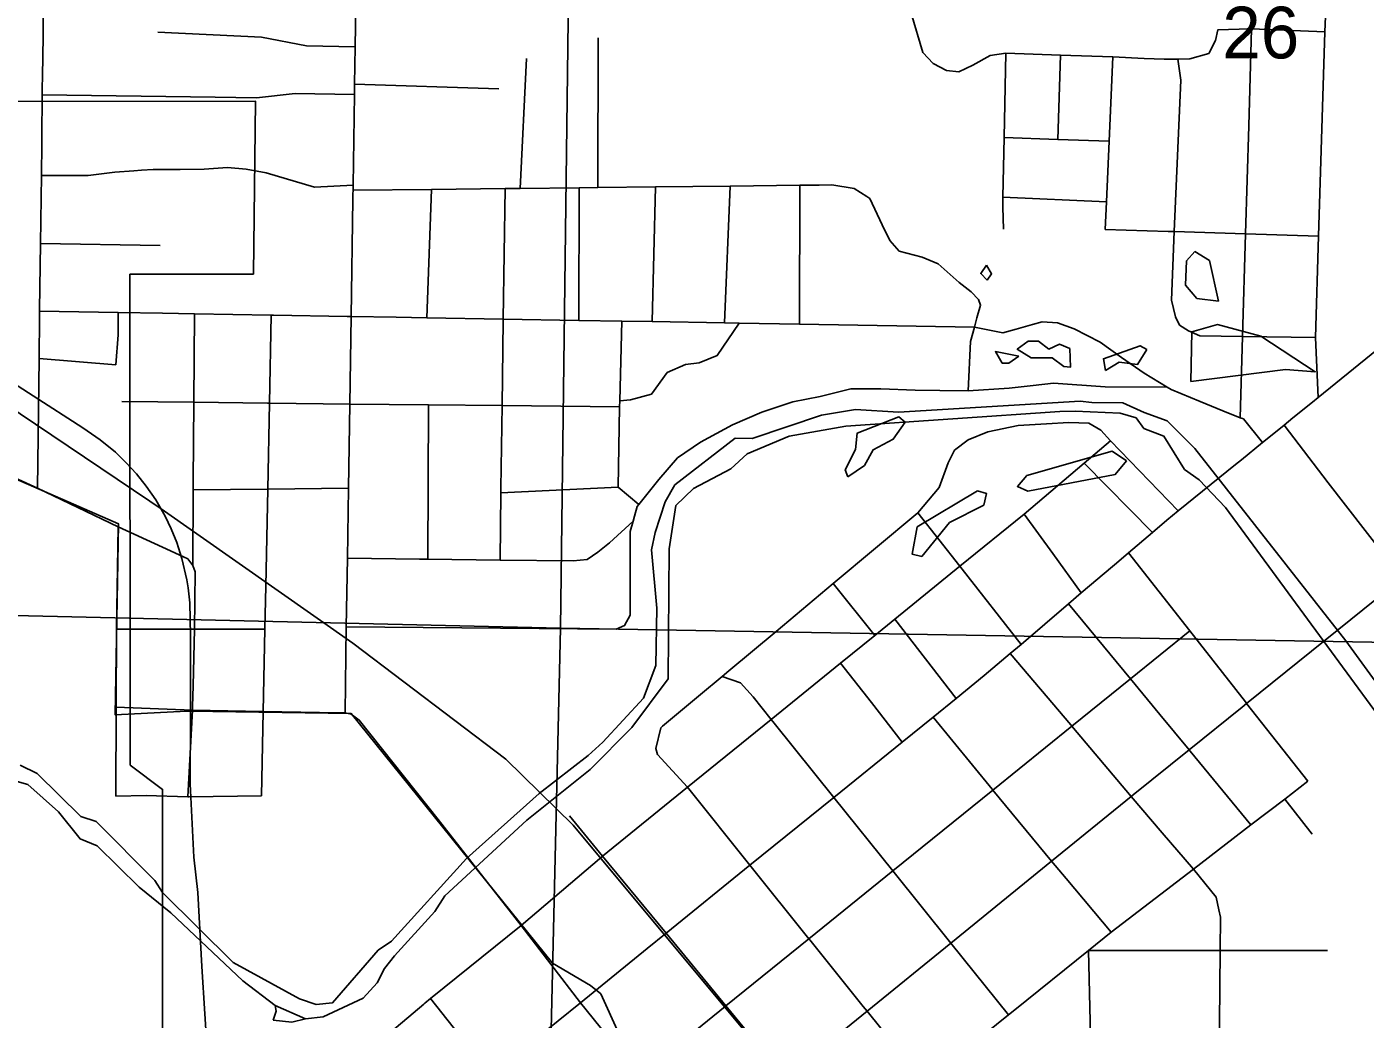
# Model space of a CAD drawing. Extents: x 0 to 68.9, y -26.1 to 22.
# Drawn here: x 4.831 to 5.914, y 17.583 to 18.387 of the extents above; entities that cross this region are included whole.
import ezdxf

# ---------------------------------------------------------------- set-up
doc = ezdxf.new("R2010")
doc.units = 0
for name, color, linetype in [('GM_X_City_Street', 7, 'Continuous'), ('GM_X_Corporation', 7, 'Continuous'), ('GM_X_County_Road', 7, 'Continuous'), ('GM_X_Major_River', 7, 'Continuous'), ('GM_X_Minor_Lake', 7, 'Continuous'), ('GM_X_Rail_Line', 7, 'Continuous'), ('GM_X_Section_Text', 7, 'Continuous'), ('GM_X_State_Route', 7, 'Continuous')]:
    doc.layers.add(name, color=color, linetype=linetype)

msp = doc.modelspace()

# ---------------------------------------------------------------- linework, layer by layer
at = {"layer": 'GM_X_City_Street'}
for p, q in [((5.293, 18.2569), (5.2933, 18.3781)), ((5.6653, 18.2958), (5.6675, 18.364)), ((5.23, 18.2562), (5.2351, 18.3613)), ((5.0961, 18.3405), (5.2127, 18.3369)), ((5.1546, 18.1514), (5.1582, 18.2554)), ((5.2775, 18.1493), (5.2778, 18.2567)), ((5.337, 18.1483), (5.3396, 18.2574)), ((5.3954, 18.1473), (5.4, 18.2581)), ((5.4561, 18.1463), (5.4565, 18.2588)), ((5.6209, 18.2491), (5.7047, 18.2454)), ((4.8418, 18.2115), (4.9386, 18.21)), ((4.8407, 18.1184), (4.9029, 18.1134)), ((5.1553, 17.956), (5.1558, 18.0809)), ((5.7419, 17.9776), (5.6867, 18.0338)), ((5.2145, 18.0096), (5.3093, 18.0143)), ((5.5171, 17.8943), (5.4835, 17.9362)), ((4.9031, 17.8361), (4.9648, 17.8338)), ((4.9611, 17.7635), (4.9648, 17.8338)), ((5.8712, 17.7332), (5.8489, 17.7618)), ((5.2895, 17.7245), (5.27, 17.7483)), ((5.5078, 17.5939), (5.4645, 17.6479)), ((5.2066, 17.5386), (5.1575, 17.6003)), ((5.3266, 17.5377), (5.3959, 17.5937))]:
    msp.add_line(p, q, dxfattribs=at)
for points in [[(5.6231, 18.3657), (5.6105, 18.3638), (5.5966, 18.3559), (5.5851, 18.3505), (5.5752, 18.3516), (5.5644, 18.3573), (5.556, 18.3663), (5.5465, 18.398), (5.5384, 18.425), (5.5382, 18.4417), (5.5423, 18.4537), (5.558, 18.4677), (5.5655, 18.4782), (5.5677, 18.4883), (5.5701, 18.59), (5.5755, 18.8267)], [(5.8128, 18.0705), (5.8148, 18.1363), (5.8172, 18.2193), (5.8198, 18.3067), (5.8221, 18.3854)], [(5.8185, 18.3853), (5.8221, 18.3854), (5.8815, 18.3829)], [(4.9367, 18.3826), (5.0208, 18.3785), (5.057, 18.3717), (5.0966, 18.3709)], [(5.6231, 18.3657), (5.6675, 18.364), (5.7099, 18.3627), (5.7351, 18.3612), (5.7514, 18.3608), (5.7624, 18.3609), (5.7633, 18.3609), (5.772, 18.3611), (5.7874, 18.3653), (5.7929, 18.3758), (5.7948, 18.3846), (5.812, 18.3851), (5.8185, 18.3853)], [(5.6213, 18.2232), (5.6208, 18.2411), (5.6209, 18.2491), (5.6218, 18.2973), (5.6231, 18.3657)], [(5.7037, 18.223), (5.7047, 18.2454), (5.7069, 18.2944), (5.7099, 18.3627)], [(5.7595, 18.2212), (5.7648, 18.3438), (5.7624, 18.3609)], [(4.8432, 18.3319), (4.9833, 18.3299), (5.0167, 18.3296), (5.0479, 18.3329), (5.096, 18.3322)], [(5.6218, 18.2973), (5.6653, 18.2958), (5.7069, 18.2944)], [(4.8425, 18.2666), (4.8803, 18.2665), (4.9021, 18.2693), (4.9173, 18.2704), (4.9235, 18.2708), (4.9329, 18.2714), (4.9549, 18.2715), (4.9742, 18.2716), (4.9933, 18.273), (5.0084, 18.2717), (5.0246, 18.2689), (5.0637, 18.2571), (5.0948, 18.2589)], [(5.0948, 18.2546), (5.1582, 18.2554), (5.2178, 18.256), (5.23, 18.2562), (5.2778, 18.2567), (5.293, 18.2569), (5.3396, 18.2574), (5.4, 18.2581), (5.4565, 18.2588), (5.4722, 18.2589), (5.4824, 18.2591), (5.5005, 18.2562), (5.5107, 18.2495)], [(5.2138, 17.9553), (5.2145, 18.0096), (5.2145, 18.0135), (5.2154, 18.0803), (5.2163, 18.1493), (5.2164, 18.1504), (5.2178, 18.256)], [(5.5107, 18.2495), (5.5132, 18.2479), (5.5231, 18.2266), (5.5292, 18.2139), (5.5369, 18.2053), (5.5554, 18.2006), (5.5685, 18.1952), (5.5855, 18.1799), (5.5951, 18.1724), (5.601, 18.1661), (5.6027, 18.1615), (5.5998, 18.1513), (5.5978, 18.1439), (5.5946, 18.1321), (5.5926, 18.0922)], [(5.7037, 18.223), (5.7545, 18.2213), (5.7595, 18.2212), (5.8172, 18.2193), (5.8764, 18.2174)], [(5.8738, 18.1354), (5.8148, 18.1363), (5.7801, 18.1368), (5.771, 18.1408), (5.7639, 18.1455), (5.7606, 18.1521), (5.7572, 18.1658), (5.7595, 18.2212)], [(4.8411, 18.1568), (4.9046, 18.1557), (4.9407, 18.1551), (4.9664, 18.1546), (5.0286, 18.1536), (5.0303, 18.1535), (5.09, 18.1525), (5.0932, 18.1525), (5.1298, 18.1518), (5.1546, 18.1514), (5.2164, 18.1504), (5.2775, 18.1493), (5.3123, 18.1487), (5.337, 18.1483), (5.3954, 18.1473), (5.4073, 18.1471), (5.4561, 18.1463), (5.5978, 18.1439), (5.6209, 18.1393), (5.6316, 18.1421), (5.6447, 18.146), (5.6527, 18.1481), (5.6649, 18.1474), (5.6785, 18.1425), (5.6996, 18.1318), (5.7168, 18.1193), (5.7352, 18.1067), (5.7538, 18.0952), (5.757, 18.0933), (5.7804, 18.0836), (5.7989, 18.076), (5.8128, 18.0705), (5.8155, 18.0695), (5.831, 18.0503)], [(4.9029, 18.1134), (4.9048, 18.1377), (4.9046, 18.1557)], [(4.9651, 17.9508), (4.9655, 18.012), (4.9655, 18.0188), (4.966, 18.083), (4.9664, 18.1546)], [(5.0207, 17.7643), (5.0221, 17.8327), (5.0235, 17.8992), (5.0242, 17.934), (5.0258, 18.0127), (5.0272, 18.0824), (5.0286, 18.1536)], [(5.3261, 18.0003), (5.3093, 18.0143), (5.3106, 18.0793), (5.3107, 18.0842), (5.3123, 18.1487)], [(5.3107, 18.0842), (5.3195, 18.0851), (5.3363, 18.0895), (5.3491, 18.1072), (5.364, 18.1137), (5.3749, 18.115), (5.3896, 18.121), (5.4073, 18.1471)], [(5.0893, 17.9013), (5.3077, 17.8992), (5.3146, 17.9024), (5.319, 17.9106), (5.3192, 17.9783), (5.3216, 17.9868), (5.3227, 17.9909), (5.3248, 17.9986), (5.3261, 18.0003), (5.3422, 18.0205), (5.3575, 18.0379), (5.3761, 18.0506), (5.402, 18.0647), (5.4258, 18.075), (5.4508, 18.0833), (5.4729, 18.0876), (5.4978, 18.094), (5.5221, 18.094), (5.5497, 18.0928), (5.5698, 18.0926), (5.5926, 18.0922), (5.6259, 18.0944), (5.6454, 18.0966), (5.6619, 18.0985), (5.7037, 18.0956), (5.7538, 18.0952)], [(4.9077, 18.0837), (4.966, 18.083), (5.0256, 18.0824), (5.0272, 18.0824), (5.0921, 18.0816), (5.1558, 18.0809), (5.2154, 18.0803), (5.3106, 18.0793)], [(5.3655, 17.7713), (5.3413, 17.7978), (5.34, 17.8028), (5.3439, 17.8194), (5.3454, 17.8207), (5.376, 17.8463), (5.3935, 17.8609), (5.399, 17.8655), (5.4372, 17.8975), (5.4835, 17.9362), (5.552, 17.9935), (5.5692, 18.014), (5.5765, 18.0339), (5.5817, 18.0441), (5.5926, 18.0526), (5.6087, 18.059), (5.6332, 18.0642), (5.6561, 18.0656), (5.6741, 18.0667), (5.6903, 18.0661), (5.7002, 18.0605), (5.708, 18.0518), (5.7627, 17.995)], [(5.9439, 17.9405), (5.8842, 18.0179), (5.8484, 18.0644)], [(5.2309, 17.6594), (5.2962, 17.7151), (5.2968, 17.7156), (5.3655, 17.7713), (5.4333, 17.8263), (5.4895, 17.8719), (5.5171, 17.8943), (5.5333, 17.9074), (5.586, 17.9502), (5.6381, 17.9924), (5.6867, 18.0338), (5.708, 18.0518)], [(4.9655, 18.012), (5.0258, 18.0127), (5.0911, 18.0134)], [(5.0902, 17.9568), (5.1485, 17.9561), (5.1553, 17.956), (5.2138, 17.9553), (5.273, 17.9546), (5.2844, 17.9558), (5.2929, 17.9616), (5.3023, 17.9693), (5.3216, 17.9868)], [(5.6355, 17.887), (5.5878, 17.9479), (5.586, 17.9502), (5.552, 17.9935)], [(5.6843, 17.9286), (5.6612, 17.9605), (5.6381, 17.9924)], [(4.9027, 17.7642), (4.9031, 17.8361), (4.9034, 17.8994), (4.9048, 17.9822)], [(5.8676, 17.7762), (5.8181, 17.8392), (5.8171, 17.8405), (5.772, 17.8979), (5.7224, 17.961)], [(5.8216, 17.7409), (5.7724, 17.8005), (5.7715, 17.8017), (5.7478, 17.8303), (5.7241, 17.8591), (5.674, 17.9198)], [(4.9034, 17.8994), (4.9665, 17.8993), (5.0235, 17.8992)], [(5.3959, 17.5937), (5.3966, 17.5943), (5.4638, 17.6487), (5.5318, 17.7036), (5.6126, 17.769), (5.6766, 17.8208), (5.7241, 17.8591), (5.772, 17.8979)], [(5.5829, 17.8432), (5.5581, 17.8753), (5.5333, 17.9074)], [(5.775, 17.7051), (5.7498, 17.7345), (5.7246, 17.7639), (5.6766, 17.8208), (5.6757, 17.8218), (5.6513, 17.8507), (5.6268, 17.8797)], [(5.5392, 17.8078), (5.5144, 17.8399), (5.4895, 17.8719)], [(5.6254, 17.587), (5.5787, 17.6451), (5.5318, 17.7036), (5.484, 17.7631), (5.4358, 17.8231), (5.4333, 17.8263), (5.4187, 17.8445), (5.4084, 17.8558), (5.3935, 17.8609)], [(5.7084, 17.6539), (5.6719, 17.6975), (5.6602, 17.7115), (5.6126, 17.769), (5.612, 17.7697), (5.5643, 17.8281)], [(5.4645, 17.6479), (5.4638, 17.6487), (5.4161, 17.7081), (5.3655, 17.7713)], [(5.4903, 17.4782), (5.4915, 17.4793), (5.5573, 17.5322), (5.6254, 17.587), (5.6305, 17.5912), (5.6901, 17.6392), (5.7084, 17.6539), (5.775, 17.7051), (5.8216, 17.7409), (5.8489, 17.7618), (5.8676, 17.7762)], [(4.9027, 17.7642), (4.9274, 17.7646), (4.9611, 17.7635)], [(4.9611, 17.7635), (4.9621, 17.7635), (5.0207, 17.7643)], [(5.3482, 17.6531), (5.3417, 17.661), (5.2968, 17.7156), (5.2895, 17.7245)], [(5.7945, 17.378), (5.7948, 17.4138), (5.7952, 17.4577), (5.7954, 17.4834), (5.7956, 17.5176), (5.7961, 17.5728), (5.7962, 17.5803), (5.7967, 17.6391), (5.7969, 17.6661), (5.7956, 17.6722), (5.7934, 17.6822), (5.775, 17.7051)], [(5.1529, 17.5964), (5.1575, 17.6003), (5.2309, 17.6594)], [(5.6901, 17.6392), (5.7919, 17.6391), (5.7967, 17.6391), (5.8835, 17.6391)], [(5.6964, 17.3809), (5.6944, 17.4602), (5.693, 17.5199), (5.6915, 17.5817), (5.6901, 17.6392)], [(5.0234, 17.4872), (5.09, 17.5434), (5.1521, 17.5958), (5.1529, 17.5964)], [(5.5573, 17.5322), (5.5109, 17.5899), (5.5078, 17.5939)]]:
    msp.add_lwpolyline(points, dxfattribs=at)
at = {"layer": 'GM_X_Corporation'}
for points in [[(4.2714, 18.9289), (5.2753, 18.9061), (5.2626, 17.9001), (4.25, 17.9235)], [(5.2753, 18.9061), (6.2983, 18.8857), (6.2791, 17.8826), (5.2626, 17.9001)], [(4.25, 17.9235), (5.2626, 17.9001), (5.2394, 16.9012), (5.2285, 16.9015), (4.2396, 16.9168)], [(5.2626, 17.9001), (6.2791, 17.8826), (6.2515, 16.877), (5.2394, 16.9012)]]:
    msp.add_lwpolyline(points, close=True, dxfattribs=at)
msp.add_lwpolyline([(4.8955, 16.7462), (4.9363, 16.8211), (4.9753, 16.8781), (4.9913, 16.8976), (4.9867, 16.8988), (5.0362, 16.9477), (5.0772, 16.9868), (5.077, 17.4014), (4.9407, 17.4014), (4.9406, 17.7695), (4.9143, 17.7892), (4.9142, 18.1867), (5.0142, 18.1868), (5.0159, 18.3267), (4.7829, 18.3266)], dxfattribs=at)
at = {"layer": 'GM_X_County_Road'}
for points in [[(5.876, 18.0868), (5.8738, 18.1354), (5.8764, 18.2174), (5.8815, 18.3829), (5.8901, 18.5795), (5.899, 18.8376), (5.9152, 18.8864), (5.9326, 18.9401)], [(5.8144, 17.8362), (5.8181, 17.8392), (5.9439, 17.9405), (6.1076, 18.0723)], [(5.4447, 17.536), (5.5109, 17.5899), (5.5787, 17.6451), (5.6602, 17.7115), (5.7246, 17.7639), (5.7263, 17.7653), (5.7715, 17.8017), (5.8144, 17.8362)], [(5.5705, 17.3835), (5.5356, 17.4258), (5.4915, 17.4793), (5.4447, 17.536), (5.3966, 17.5943), (5.3482, 17.6531)]]:
    msp.add_lwpolyline(points, dxfattribs=at)
at = {"layer": 'GM_X_Major_River'}
msp.add_line((5.0318, 17.5946), (5.0563, 17.5837), dxfattribs=at)
for points in [[(5.6075, 18.194), (5.6029, 18.1872), (5.6081, 18.1818)], [(5.6081, 18.1818), (5.6116, 18.1871), (5.6075, 18.194)], [(5.6336, 18.1203), (5.6147, 18.124), (5.6202, 18.1148)], [(5.6202, 18.1148), (5.6256, 18.1147), (5.6336, 18.1203)], [(5.7353, 18.0746), (5.7178, 18.0826), (5.6927, 18.0827), (5.6833, 18.084), (5.5364, 18.075), (5.5015, 18.0771), (5.474, 18.0726), (5.4179, 18.0538), (5.4042, 18.054), (5.3553, 18.0161), (5.3474, 18.0025), (5.3394, 17.9776), (5.3365, 17.9635), (5.3407, 17.9163), (5.3399, 17.87), (5.3299, 17.8435), (5.297, 17.8079), (5.2851, 17.7971), (5.2454, 17.7662), (5.1867, 17.7136), (5.1259, 17.6466), (5.1152, 17.6395), (5.0783, 17.5968), (5.065, 17.5955), (5.0514, 17.5999), (4.9979, 17.6293), (4.9407, 17.6862), (4.9344, 17.6958), (4.887, 17.7437), (4.8745, 17.7477), (4.839, 17.7825), (4.8254, 17.7892)], [(5.0563, 17.5837), (5.0705, 17.5855), (5.1031, 17.6006), (5.1143, 17.6129), (5.1202, 17.6246), (5.1284, 17.6347), (5.1609, 17.6707), (5.1691, 17.6835), (5.2355, 17.7447), (5.2868, 17.7857), (5.3204, 17.8197), (5.35, 17.8591), (5.3506, 17.9644), (5.3561, 17.9993), (5.3704, 18.0132), (5.4007, 18.029), (5.4138, 18.0413), (5.4479, 18.0556), (5.4937, 18.0636), (5.6668, 18.0755), (5.6793, 18.0757), (5.7158, 18.0743), (5.7286, 18.0703), (5.735, 18.0618)], [(6.4876, 17.4291), (6.4643, 17.3672), (6.4404, 17.3506), (6.4136, 17.3442), (6.4014, 17.3418), (6.3763, 17.3441), (6.0939, 17.4272), (6.0592, 17.4457), (6.0092, 17.48), (5.9998, 17.4874), (5.9904, 17.4944), (5.954, 17.5425), (5.9508, 17.5547), (5.9511, 17.5669), (5.9565, 17.5926), (6.0013, 17.6294), (6.0172, 17.6409), (6.0231, 17.6548), (6.0331, 17.6816), (6.0221, 17.7198), (5.8985, 17.8899), (5.7761, 18.0456), (5.7537, 18.068), (5.7353, 18.0746)], [(5.735, 18.0618), (5.7512, 18.0555), (5.7678, 18.0287), (5.7798, 18.0201), (5.8011, 17.9977), (6.0224, 17.6962)], [(4.7887, 17.7535), (4.8191, 17.7771), (4.8316, 17.7735), (4.8563, 17.7514), (4.8738, 17.7295), (4.8878, 17.7239), (4.9218, 17.6903), (4.9473, 17.6697), (5.0057, 17.6147), (5.0318, 17.5946)], [(5.0563, 17.5837), (5.0318, 17.5946), (5.0325, 17.5901), (5.0302, 17.5828)], [(5.0302, 17.5828), (5.0453, 17.5812), (5.0563, 17.5837)]]:
    msp.add_lwpolyline(points, dxfattribs=at)
at = {"layer": 'GM_X_Minor_Lake'}
for points in [[(5.7761, 18.2051), (5.7695, 18.1975), (5.7686, 18.1778), (5.7779, 18.167), (5.7953, 18.1649)], [(5.7953, 18.1649), (5.7881, 18.1977), (5.7761, 18.2051)], [(5.8296, 18.1364), (5.7944, 18.1459), (5.7738, 18.1401), (5.7729, 18.0998)], [(5.7729, 18.0998), (5.8497, 18.1095), (5.8736, 18.1077), (5.8296, 18.1364)], [(5.6579, 18.126), (5.6496, 18.1325), (5.6412, 18.1326), (5.6324, 18.1259), (5.6437, 18.1189), (5.6608, 18.1191), (5.6702, 18.1121)], [(5.6702, 18.1121), (5.6755, 18.1113), (5.6749, 18.1265), (5.6666, 18.13), (5.6579, 18.126)], [(5.7372, 18.1257), (5.7319, 18.1288), (5.7022, 18.1182), (5.704, 18.1087)], [(5.704, 18.1087), (5.715, 18.1154), (5.7298, 18.1137), (5.7372, 18.1257)], [(5.5418, 18.067), (5.5365, 18.0712), (5.5029, 18.058), (5.5016, 18.0447), (5.4931, 18.0284), (5.4953, 18.0227)], [(5.4953, 18.0227), (5.5087, 18.0317), (5.5157, 18.0445), (5.5321, 18.053), (5.5418, 18.067)], [(5.7209, 18.0355), (5.7093, 18.0433), (5.6403, 18.0236)], [(5.6403, 18.0236), (5.6326, 18.0149), (5.6409, 18.011), (5.7117, 18.0246), (5.7209, 18.0355)], [(5.6003, 18.0112), (5.5514, 17.9821), (5.5473, 17.9601), (5.5553, 17.9581)], [(5.5553, 17.9581), (5.5776, 17.9856), (5.6055, 17.9997), (5.6075, 18.0092), (5.6003, 18.0112)]]:
    msp.add_lwpolyline(points, dxfattribs=at)
at = {"layer": 'GM_X_Rail_Line'}
for p, q in [((4.9304, 18.0029), (4.9394, 17.9967)), ((4.9628, 17.8329), (4.96, 17.8329))]:
    msp.add_line(p, q, dxfattribs=at)
for points in [[(4.9304, 18.0029), (4.5219, 18.278), (3.9213, 18.739), (3.5195, 19.0528), (3.0238, 19.4269), (2.3664, 19.9252), (1.927, 20.2517)], [(4.96, 17.8329), (4.9023, 17.8299), (4.905, 17.9845), (4.6094, 18.1135), (3.5465, 18.441), (3.4843, 18.4615), (3.4425, 18.4786), (3.4016, 18.5067), (3.3614, 18.5468), (3.3023, 18.6209), (3.1558, 18.8), (2.8841, 19.0797), (2.8257, 19.1387), (2.6615, 19.27), (2.3538, 19.5236), (2.1141, 19.7092), (1.927, 19.8578)], [(4.9773, 17.5496), (4.9725, 17.6262), (4.9692, 17.686), (4.966, 17.7148), (4.9629, 17.7742), (4.9631, 17.8285), (4.9631, 17.8941), (4.9626, 17.9207), (4.9613, 17.9327), (4.9603, 17.9392), (4.9563, 17.9566), (4.9522, 17.9696), (4.9476, 17.9806), (4.9426, 17.9908), (4.9351, 18.0041), (4.9274, 18.015), (4.9195, 18.025), (4.9112, 18.0341), (4.9025, 18.0426), (4.8902, 18.0526), (4.8761, 18.0622), (4.8359, 18.0883), (4.711, 18.1686)], [(4.9394, 17.9967), (5.0946, 17.8881), (5.2186, 17.7941), (5.273, 17.7405), (5.5573, 17.3992), (5.5713, 17.3713), (5.5838, 17.3379), (5.5811, 17.094)], [(5.445, 17.1161), (5.4508, 17.3932), (5.3099, 17.5719), (5.2953, 17.604), (5.287, 17.6109), (5.2563, 17.629), (5.0933, 17.831), (4.9628, 17.8329)]]:
    msp.add_lwpolyline(points, dxfattribs=at)
at = {"layer": 'GM_X_State_Route'}
for p, q in [((4.9048, 17.9822), (4.8394, 18.0134)), ((4.9406, 17.9656), (4.9048, 17.9822)), ((5.0883, 17.8315), (5.0676, 17.8319)), ((5.2788, 17.5969), (5.3329, 17.6407))]:
    msp.add_line(p, q, dxfattribs=at)
for points in [[(5.0947, 18.2516), (5.0948, 18.2546), (5.0948, 18.2589), (5.096, 18.3322), (5.0961, 18.3405), (5.0966, 18.3709), (5.0989, 18.5248), (5.099, 18.5289)], [(4.8436, 18.3575), (4.8442, 18.4127), (4.8443, 18.4167)], [(4.8428, 18.2973), (4.8432, 18.3319), (4.8435, 18.3525), (4.8436, 18.3575)], [(4.8411, 18.1578), (4.8418, 18.2115), (4.8425, 18.2666), (4.8428, 18.2924), (4.8428, 18.2973)], [(5.0883, 17.8315), (5.0893, 17.9013), (5.0902, 17.9568), (5.0911, 18.0134), (5.0921, 18.0816), (5.0932, 18.1525), (5.0947, 18.2475), (5.0947, 18.2516)], [(5.8139, 18.0365), (5.831, 18.0503), (5.8402, 18.0578), (5.8484, 18.0644), (5.8556, 18.0703), (5.8713, 18.083), (5.876, 18.0868), (5.9805, 18.1715), (5.9894, 18.1787), (6.0152, 18.1996), (6.0159, 18.2002), (6.0526, 18.202), (6.1108, 18.2049)], [(4.8394, 18.0134), (4.8407, 18.1184), (4.8411, 18.152), (4.8411, 18.1568), (4.8411, 18.1578)], [(4.7379, 18.0596), (4.7468, 18.0555), (4.8394, 18.0134)], [(5.7128, 17.9528), (5.7224, 17.961), (5.7419, 17.9776), (5.7535, 17.9875), (5.7627, 17.995), (5.8092, 18.0327), (5.8139, 18.0365)], [(4.9653, 17.8533), (4.9665, 17.8993), (4.9671, 17.9458), (4.9651, 17.9508), (4.961, 17.9562), (4.954, 17.9594), (4.9406, 17.9656)], [(5.3329, 17.6407), (5.3482, 17.6531), (5.4161, 17.7081), (5.484, 17.7631), (5.5392, 17.8078), (5.5643, 17.8281), (5.5829, 17.8432), (5.6057, 17.8617), (5.6268, 17.8797), (5.6355, 17.887), (5.674, 17.9198), (5.6843, 17.9286), (5.7096, 17.9501), (5.7128, 17.9528)], [(4.9648, 17.8338), (4.9649, 17.8367), (4.9653, 17.8533)], [(5.0676, 17.8319), (5.0221, 17.8327), (4.9648, 17.8338)], [(5.2788, 17.5969), (5.2309, 17.6594), (5.1637, 17.7453), (5.0998, 17.8257), (5.0933, 17.8306), (5.0883, 17.8315)], [(5.085, 17.4406), (5.1388, 17.484), (5.2066, 17.5386), (5.2788, 17.5969)], [(5.3741, 17.4788), (5.3266, 17.5377), (5.2788, 17.5969)]]:
    msp.add_lwpolyline(points, dxfattribs=at)

# ---------------------------------------------------------------- texts
at = {"layer": 'GM_X_Section_Text'}
msp.add_text('26', height=0.04186, rotation=0, dxfattribs=at).set_placement((5.7984, 18.3614))

doc.saveas('drawing.dxf')
